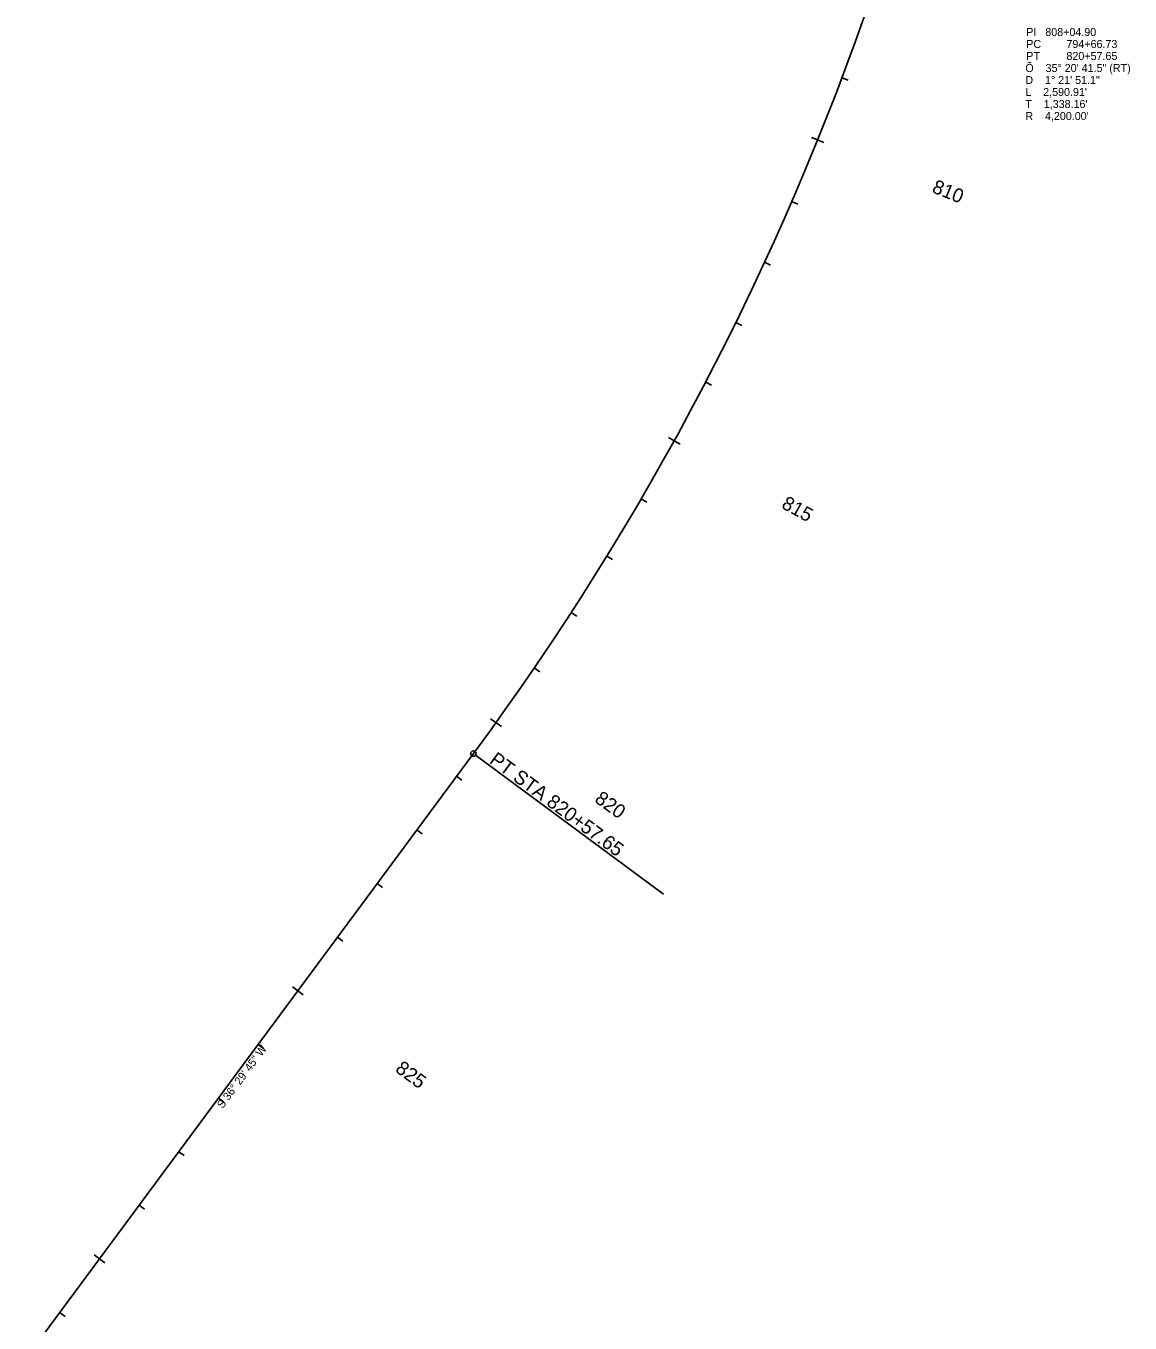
# Model space of a CAD drawing. Extents: x 2819977 to 2827606, y 113942 to 150283.
# Drawn here: x 2822208 to 2823862, y 136141 to 138086 of the extents above; entities that cross this region are included whole.
import ezdxf

# ---------------------------------------------------------------- set-up
doc = ezdxf.new("R2010")
doc.units = 0
for name, color, linetype in [('Level 63', 7, 'Continuous'), ('Roadway-Safety', 7, 'Continuous'), ('Roadway-Signs', 7, 'Continuous'), ('Roadway-Walls', 7, 'Continuous'), ('Utility-Power', 7, 'Continuous')]:
    doc.layers.add(name, color=color, linetype=linetype)

msp = doc.modelspace()

# ---------------------------------------------------------------- linework, layer by layer
at = {"layer": 'Level 63'}
msp.add_circle((2822878.3, 136994.9), 4, dxfattribs=at)
at = {"layer": 'Roadway-Safety'}
msp.add_line((2822881.5, 136992.5), (2823163.3, 136784.1), dxfattribs=at)
at = {"layer": 'Utility-Power'}
for p, q in [((2823430.7, 138008.1), (2823440, 138004.5)), ((2823394.2, 137915), (2823384.9, 137918.7)), ((2823394.2, 137915), (2823403.5, 137911.2)), ((2823355.5, 137822.8), (2823364.7, 137818.8)), ((2823314.7, 137731.5), (2823323.8, 137727.3)), ((2823271.7, 137641.2), (2823280.6, 137636.8)), ((2823226.5, 137552), (2823235.4, 137547.4)), ((2823179.3, 137463.9), (2823170.5, 137468.7)), ((2823179.3, 137463.9), (2823188, 137459)), ((2823129.9, 137376.9), (2823138.5, 137371.9)), ((2823078.5, 137291.1), (2823087, 137285.9)), ((2823025.1, 137206.6), (2823033.5, 137201.1)), ((2822969.6, 137123.4), (2822977.9, 137117.7)), ((2822912.2, 137041.5), (2822904.1, 137047.3)), ((2822912.2, 137041.5), (2822920.4, 137035.6)), ((2822878.3, 136994.9), (2822207.8, 136088.7)), ((2822853.1, 136960.9), (2822861.1, 136954.9)), ((2822793.6, 136880.5), (2822801.6, 136874.5)), ((2822734.1, 136800.1), (2822742.2, 136794.1)), ((2822674.7, 136719.7), (2822682.7, 136713.7)), ((2822615.2, 136639.3), (2822607.1, 136645.2)), ((2822615.2, 136639.3), (2822623.2, 136633.3)), ((2822555.7, 136558.9), (2822563.7, 136553)), ((2822496.2, 136478.5), (2822504.3, 136472.6)), ((2822436.8, 136398.1), (2822444.8, 136392.2)), ((2822377.3, 136317.7), (2822385.3, 136311.8)), ((2822317.8, 136237.3), (2822309.8, 136243.3)), ((2822317.8, 136237.3), (2822325.8, 136231.4)), ((2822258.3, 136157), (2822266.4, 136151))]:
    msp.add_line(p, q, dxfattribs=at)
msp.add_arc((2819501.9, 139492.9), 4200, 323.5041, 358.849, dxfattribs=at)

# ---------------------------------------------------------------- texts
at = {"layer": 'Roadway-Safety'}
msp.add_text('PT STA 820+57.65', height=21, rotation=323.5041, dxfattribs=at).set_placement((2822901, 136981.9))
at = {"layer": 'Roadway-Signs'}
msp.add_text('S 36%%d 29\' 45" W', height=12, rotation=53.5041, dxfattribs=at).set_placement((2822502.6, 136461.9))
at = {"layer": 'Roadway-Walls'}
for s, p in [('PI   808+04.90', (2823706.9, 138070.8)), ('PC', (2823706.9, 138052.8)), ('794+66.73', (2823767.1, 138052.8)), ('Õ    35%%d 20\' 41.5" (RT)', (2823705.5, 138016.8)), ('PT', (2823706.9, 138034.8)), ('820+57.65', (2823767.1, 138034.8)), ('D    1%%d 21\' 51.1"', (2823705.5, 137998.8)), ("T    1,338.16'", (2823705.5, 137962.8)), ("L    2,590.91'", (2823705.5, 137980.8)), ("R    4,200.00'", (2823705.5, 137944.8))]:
    msp.add_text(s, height=12, dxfattribs=at).set_placement(p)
at = {"layer": 'Utility-Power'}
for s, rotation, p in [(' 810', 337.9324, (2823557.1, 137839.8)), (' 815', 331.1114, (2823331.8, 137367.7)), (' 820', 324.2905, (2823052.3, 136927.9)), (' 825', 323.5041, (2822753.6, 136523.8))]:
    msp.add_text(s, height=21, rotation=rotation, dxfattribs=at).set_placement(p)

doc.saveas('drawing.dxf')
